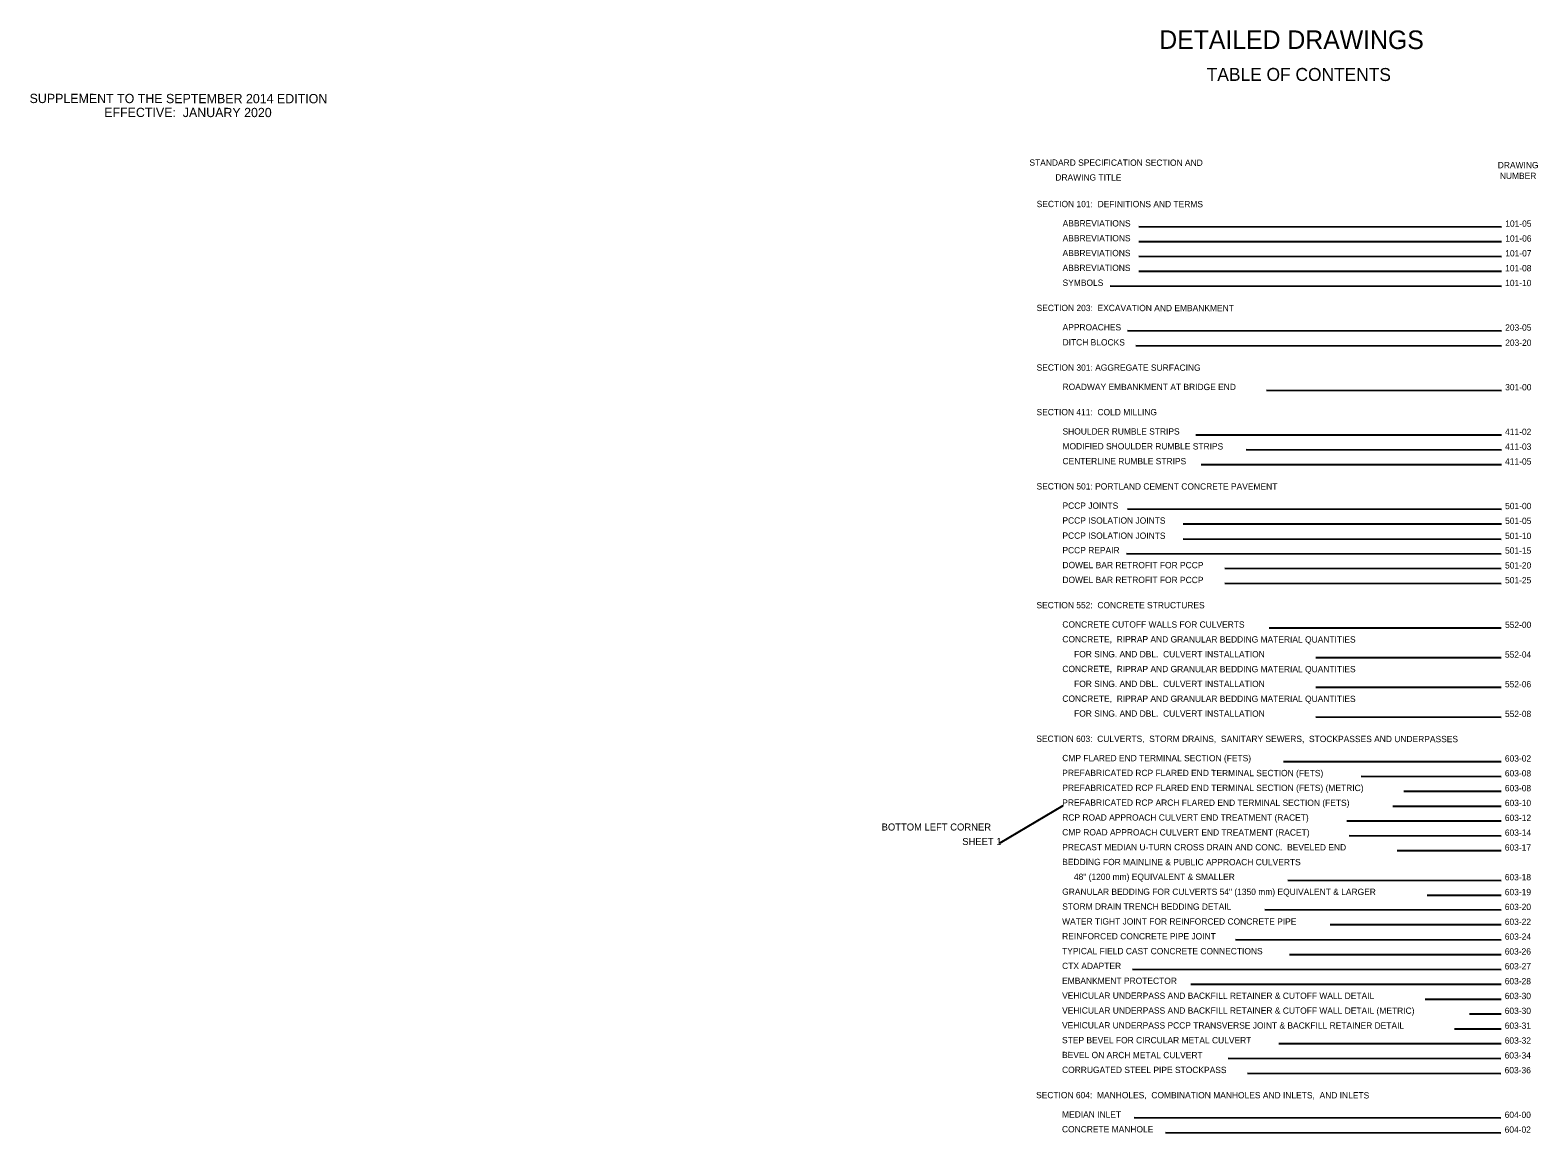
# Model space of a CAD drawing. Extents: x 49987.3 to 50007.6, y 49951 to 50011.
# Drawn here: x 49987.26 to 50007.59, y 49996.16 to 50011.01 of the extents above; entities that cross this region are included whole.
import ezdxf

# ---------------------------------------------------------------- set-up
doc = ezdxf.new("R2010")
doc.units = 0
doc.layers.add('Default', color=7, linetype='Continuous')
doc.layers.add('Level 1', color=7, linetype='Continuous')

msp = doc.modelspace()

# ---------------------------------------------------------------- linework, layer by layer
at = {"layer": 'Default'}
for p in [(50001.184, 50000.563), (50000.336, 50000.062)]:
    msp.add_line(p, (50000.336, 50000.062), dxfattribs=at)
at = {"layer": 'Level 1'}
for p, q in [((50002.208, 50008.367), (50007.098, 50008.364)), ((50002.208, 50008.167), (50007.098, 50008.164)), ((50002.208, 50007.967), (50007.098, 50007.964)), ((50002.208, 50007.767), (50007.097, 50007.764)), ((50001.824, 50007.568), (50007.097, 50007.564)), ((50002.055, 50006.968), (50007.097, 50006.964)), ((50002.167, 50006.764), (50007.097, 50006.76)), ((50003.929, 50006.163), (50007.097, 50006.16)), ((50002.979, 50005.563), (50007.096, 50005.56)), ((50003.655, 50005.363), (50007.096, 50005.36)), ((50003.05, 50005.163), (50007.096, 50005.16)), ((50002.054, 50004.564), (50007.096, 50004.56)), ((50002.805, 50004.363), (50007.096, 50004.36)), ((50002.805, 50004.16), (50007.095, 50004.157)), ((50002.044, 50003.964), (50007.095, 50003.96)), ((50003.367, 50003.763), (50007.095, 50003.76)), ((50003.367, 50003.563), (50007.095, 50003.56)), ((50003.968, 50002.963), (50007.095, 50002.96)), ((50004.594, 50002.562), (50007.094, 50002.56)), ((50004.594, 50002.162), (50007.094, 50002.16)), ((50004.594, 50001.762), (50007.094, 50001.76)), ((50004.158, 50001.163), (50007.093, 50001.16)), ((50005.206, 50000.962), (50007.093, 50000.96)), ((50005.782, 50000.761), (50007.093, 50000.76)), ((50005.635, 50000.561), (50007.093, 50000.56)), ((50005.012, 50000.362), (50007.093, 50000.36)), ((50005.045, 50000.162), (50007.093, 50000.16)), ((50005.692, 49999.961), (50007.092, 49999.96)), ((50004.217, 49999.562), (50007.092, 49999.56)), ((50006.097, 49999.361), (50007.092, 49999.36)), ((50007.092, 49999.16), (50003.906, 49999.163)), ((50007.092, 49998.96), (50004.79, 49998.962)), ((50003.51, 49998.763), (50007.092, 49998.76)), ((50004.238, 49998.562), (50007.091, 49998.56)), ((50002.122, 49998.364), (50007.091, 49998.36)), ((50002.911, 49998.163), (50007.091, 49998.16)), ((50006.07, 49997.961), (50007.091, 49997.96)), ((50006.667, 49997.761), (50007.091, 49997.76)), ((50006.465, 49997.561), (50007.091, 49997.56)), ((50004.096, 49997.363), (50007.091, 49997.36)), ((50003.411, 49997.163), (50007.09, 49997.16)), ((50003.672, 49996.963), (50007.09, 49996.96)), ((50002.144, 49996.364), (50007.09, 49996.36)), ((50002.567, 49996.164), (50007.09, 49996.16))]:
    msp.add_line(p, q, dxfattribs=at)

# ---------------------------------------------------------------- texts
at = {"layer": 'Default'}
for s, p in [('BOTTOM LEFT CORNER ', (49998.742, 50000.231)), ('SHEET 1', (49999.829, 50000.036))]:
    msp.add_text(s, height=0.095, dxfattribs=at).set_placement(p)
at = {"layer": 'Level 1'}
for s, height, p in [('DETAILED DRAWINGS', 0.25, (50002.484, 50010.76)), ('TABLE OF CONTENTS', 0.175, (50003.124, 50010.329)), ('SUPPLEMENT TO THE SEPTEMBER 2014 EDITION', 0.125, (49987.257, 50010.03)), ('EFFECTIVE:  JANUARY 2020', 0.125, (49988.263, 50009.842)), ('STANDARD SPECIFICATION SECTION AND', 0.085, (50000.734, 50009.186)), ('DRAWING', 0.085, (50007.047, 50009.152)), ('DRAWING TITLE', 0.085, (50001.084, 50008.986)), ('NUMBER', 0.085, (50007.075, 50009.008)), ('SECTION 101:  DEFINITIONS AND TERMS', 0.085, (50000.832, 50008.628)), ('ABBREVIATIONS', 0.085, (50001.182, 50008.368)), ('101-05', 0.085, (50007.148, 50008.364)), ('ABBREVIATIONS', 0.085, (50001.182, 50008.168)), ('101-06', 0.085, (50007.148, 50008.164)), ('ABBREVIATIONS', 0.085, (50001.181, 50007.968)), ('101-07', 0.085, (50007.148, 50007.964)), ('ABBREVIATIONS', 0.085, (50001.181, 50007.768)), ('101-08', 0.085, (50007.147, 50007.764)), ('SYMBOLS', 0.085, (50001.181, 50007.568)), ('101-10', 0.085, (50007.147, 50007.564)), ('SECTION 203:  EXCAVATION AND EMBANKMENT', 0.085, (50000.831, 50007.228)), ('APPROACHES', 0.085, (50001.181, 50006.968)), ('203-05', 0.085, (50007.147, 50006.964)), ('DITCH BLOCKS', 0.085, (50001.181, 50006.765)), ('203-20', 0.085, (50007.147, 50006.76)), ('SECTION 301: AGGREGATE SURFACING', 0.085, (50000.831, 50006.425)), ('ROADWAY EMBANKMENT AT BRIDGE END', 0.085, (50001.181, 50006.165)), ('301-00', 0.085, (50007.147, 50006.16)), ('SECTION 411:  COLD MILLING', 0.085, (50000.83, 50005.825)), ('SHOULDER RUMBLE STRIPS', 0.085, (50001.18, 50005.565)), ('411-02', 0.085, (50007.146, 50005.56)), ('MODIFIED SHOULDER RUMBLE STRIPS       ', 0.085, (50001.18, 50005.365)), ('411-03', 0.085, (50007.146, 50005.36)), ('CENTERLINE RUMBLE STRIPS', 0.085, (50001.18, 50005.165)), ('411-05', 0.085, (50007.146, 50005.16)), ('SECTION 501: PORTLAND CEMENT CONCRETE PAVEMENT', 0.085, (50000.83, 50004.825)), ('PCCP JOINTS', 0.085, (50001.18, 50004.565)), ('501-00', 0.085, (50007.146, 50004.56)), ('PCCP ISOLATION JOINTS', 0.085, (50001.179, 50004.365)), ('501-05', 0.085, (50007.146, 50004.36)), ('PCCP ISOLATION JOINTS', 0.085, (50001.179, 50004.161)), ('501-10', 0.085, (50007.145, 50004.157)), ('PCCP REPAIR', 0.085, (50001.179, 50003.965)), ('501-15', 0.085, (50007.145, 50003.96)), ('DOWEL BAR RETROFIT FOR PCCP', 0.085, (50001.179, 50003.765)), ('501-20', 0.085, (50007.145, 50003.76)), ('DOWEL BAR RETROFIT FOR PCCP', 0.085, (50001.179, 50003.565)), ('501-25', 0.085, (50007.145, 50003.56)), ('SECTION 552:  CONCRETE STRUCTURES', 0.085, (50000.829, 50003.225)), ('CONCRETE CUTOFF WALLS FOR CULVERTS', 0.085, (50001.178, 50002.965)), ('552-00', 0.085, (50007.145, 50002.96)), ('CONCRETE,  RIPRAP AND GRANULAR BEDDING MATERIAL QUANTITIES     ', 0.085, (50001.178, 50002.765)), ('CONCRETE,  RIPRAP AND GRANULAR BEDDING MATERIAL QUANTITIES     ', 0.085, (50001.178, 50002.365)), ('     FOR SING. AND DBL.  CULVERT INSTALLATION', 0.085, (50001.178, 50002.565)), ('552-04', 0.085, (50007.144, 50002.56)), ('     FOR SING. AND DBL.  CULVERT INSTALLATION', 0.085, (50001.178, 50002.165)), ('552-06', 0.085, (50007.144, 50002.16)), ('CONCRETE,  RIPRAP AND GRANULAR BEDDING MATERIAL QUANTITIES     ', 0.085, (50001.178, 50001.965)), ('     FOR SING. AND DBL.  CULVERT INSTALLATION', 0.085, (50001.178, 50001.765)), ('552-08', 0.085, (50007.144, 50001.76)), ('SECTION 603:  CULVERTS,  STORM DRAINS,  SANITARY SEWERS,  STOCKPASSES AND UNDERPASSES  ', 0.085, (50000.827, 50001.425)), ('CMP FLARED END TERMINAL SECTION (FETS)', 0.085, (50001.177, 50001.165)), ('603-02', 0.085, (50007.143, 50001.16)), ('PREFABRICATED RCP FLARED END TERMINAL SECTION (FETS)', 0.085, (50001.177, 50000.965)), ('603-08', 0.085, (50007.143, 50000.96)), ('PREFABRICATED RCP FLARED END TERMINAL SECTION (FETS) (METRIC)', 0.085, (50001.177, 50000.765)), ('603-08', 0.085, (50007.143, 50000.76)), ('PREFABRICATED RCP ARCH FLARED END TERMINAL SECTION (FETS)', 0.085, (50001.177, 50000.565)), ('603-10', 0.085, (50007.143, 50000.56)), ('RCP ROAD APPROACH CULVERT END TREATMENT (RACET)', 0.085, (50001.177, 50000.365)), ('603-12', 0.085, (50007.143, 50000.36)), ('CMP ROAD APPROACH CULVERT END TREATMENT (RACET)', 0.085, (50001.176, 50000.165)), ('603-14', 0.085, (50007.143, 50000.16)), ('PRECAST MEDIAN U-TURN CROSS DRAIN AND CONC.  BEVELED END', 0.085, (50001.176, 49999.965)), ('603-17', 0.085, (50007.142, 49999.96)), ('BEDDING FOR MAINLINE & PUBLIC APPROACH CULVERTS', 0.085, (50001.176, 49999.765)), ('     48" (1200 mm) EQUIVALENT & SMALLER', 0.085, (50001.176, 49999.565)), ('603-18', 0.085, (50007.142, 49999.56)), ('GRANULAR BEDDING FOR CULVERTS 54" (1350 mm) EQUIVALENT & LARGER', 0.085, (50001.176, 49999.365)), ('603-19', 0.085, (50007.142, 49999.36)), ('STORM DRAIN TRENCH BEDDING DETAIL', 0.085, (50001.176, 49999.165)), ('603-20', 0.085, (50007.142, 49999.16)), ('WATER TIGHT JOINT FOR REINFORCED CONCRETE PIPE', 0.085, (50001.175, 49998.965)), ('603-22', 0.085, (50007.142, 49998.96)), ('REINFORCED CONCRETE PIPE JOINT', 0.085, (50001.175, 49998.765)), ('603-24', 0.085, (50007.142, 49998.76)), ('TYPICAL FIELD CAST CONCRETE CONNECTIONS', 0.085, (50001.175, 49998.565)), ('603-26', 0.085, (50007.141, 49998.56)), ('CTX ADAPTER', 0.085, (50001.175, 49998.365)), ('603-27', 0.085, (50007.141, 49998.36)), ('EMBANKMENT PROTECTOR', 0.085, (50001.175, 49998.165)), ('603-28', 0.085, (50007.141, 49998.16)), ('VEHICULAR UNDERPASS AND BACKFILL RETAINER & CUTOFF WALL DETAIL', 0.085, (50001.175, 49997.965)), ('603-30', 0.085, (50007.141, 49997.96)), ('VEHICULAR UNDERPASS AND BACKFILL RETAINER & CUTOFF WALL DETAIL (METRIC)', 0.085, (50001.175, 49997.765)), ('603-30', 0.085, (50007.141, 49997.76)), ('VEHICULAR UNDERPASS PCCP TRANSVERSE JOINT & BACKFILL RETAINER DETAIL', 0.085, (50001.174, 49997.565)), ('603-31', 0.085, (50007.141, 49997.56)), ('STEP BEVEL FOR CIRCULAR METAL CULVERT', 0.085, (50001.174, 49997.365)), ('603-32', 0.085, (50007.141, 49997.36)), ('BEVEL ON ARCH METAL CULVERT', 0.085, (50001.174, 49997.165)), ('603-34', 0.085, (50007.14, 49997.16)), ('CORRUGATED STEEL PIPE STOCKPASS', 0.085, (50001.174, 49996.965)), ('603-36', 0.085, (50007.14, 49996.96)), ('SECTION 604:  MANHOLES,  COMBINATION MANHOLES AND INLETS,  AND INLETS', 0.085, (50000.824, 49996.625)), ('MEDIAN INLET', 0.085, (50001.174, 49996.365)), ('604-00', 0.085, (50007.14, 49996.36)), ('CONCRETE MANHOLE', 0.085, (50001.173, 49996.165)), ('604-02', 0.085, (50007.14, 49996.16))]:
    msp.add_text(s, height=height, rotation=359.9586, dxfattribs=at).set_placement(p)

doc.saveas('drawing.dxf')
